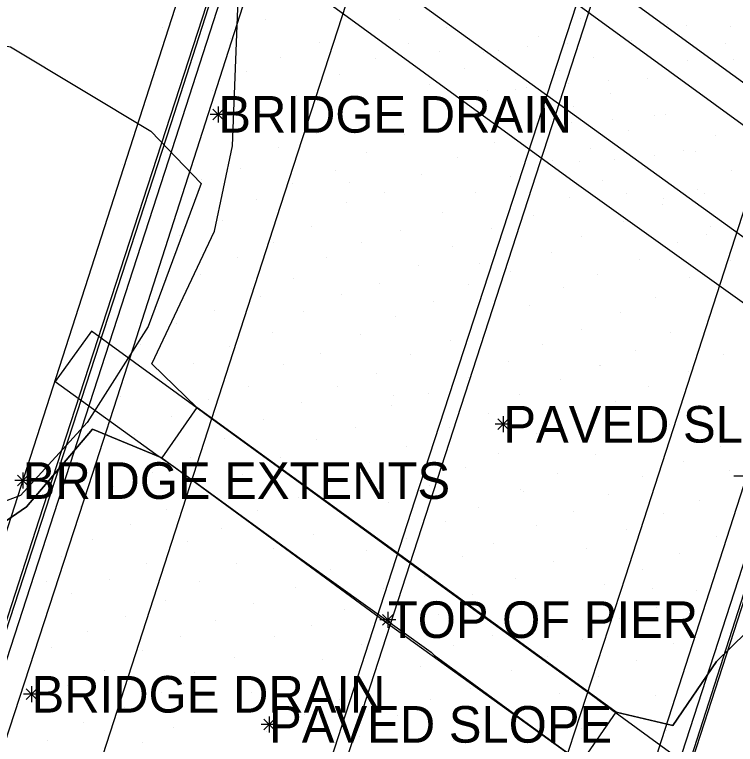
# Model space of a CAD drawing. Extents: x 0 to 1739264, y 0 to 465304.
# Drawn here: x 1738821.1 to 1738856.51, y 464637.2 to 464673.07 of the extents above; entities that cross this region are included whole.
import ezdxf

# ---------------------------------------------------------------- set-up
doc = ezdxf.new("R2010")
doc.units = 0
for name, color, linetype in [('Default', 7, 'Continuous'), ('S_Ground_SpotElevation', 7, 'Continuous'), ('S_Misc_MiscItems', 7, 'Continuous'), ('S_Terrain_Boundary', 7, 'Continuous'), ('S_Terrain_Flow_Arrows', 7, 'Continuous'), ('S_Terrain_Holes', 7, 'Continuous'), ('S_Terrain_Imported_Contours', 7, 'Continuous'), ('S_Terrain_Low_Points', 7, 'Continuous'), ('S_Terrain_Major_Contours_Label', 7, 'Continuous'), ('S_Terrain_Minor_Contours', 7, 'Continuous'), ('S_Terrain_Spots', 7, 'Continuous'), ('S_Terrain_Triangles', 7, 'Continuous'), ('S_Terrain_Voids', 7, 'Continuous'), ('S_Terrain_XSC', 7, 'Continuous'), ('S_Text', 7, 'Continuous')]:
    doc.layers.add(name, color=color, linetype=linetype)

# ---------------------------------------------------------------- blocks, each defined once
blk = doc.blocks.new('POINT_DISPLAY')
at = {"layer": 'Default'}
blk.add_line((0, 0), (0, 0), dxfattribs=at)

msp = doc.modelspace()

# ---------------------------------------------------------------- linework, layer by layer
at = {"layer": 'S_Misc_MiscItems'}
for p, q in [((1738831.105, 464668.563225), (1738831.105, 464667.777375)), ((1738831.497925, 464668.1703), (1738830.712075, 464668.1703)), ((1738831.367081, 464667.908219), (1738830.842919, 464668.432381)), ((1738831.367081, 464668.432381), (1738830.842919, 464667.908219)), ((1738845.371081, 464652.673819), (1738844.846919, 464653.197981)), ((1738845.371081, 464653.197981), (1738844.846919, 464652.673819)), ((1738845.109, 464653.328825), (1738845.109, 464652.542975)), ((1738845.501925, 464652.9359), (1738844.716075, 464652.9359)), ((1738821.499, 464650.559925), (1738821.499, 464649.774075)), ((1738821.891925, 464650.167), (1738821.106075, 464650.167)), ((1738821.761081, 464649.904919), (1738821.236919, 464650.429081)), ((1738821.761081, 464650.429081), (1738821.236919, 464649.904919)), ((1738857.224925, 464650.378), (1738856.439075, 464650.378)), ((1738839.435, 464643.723525), (1738839.435, 464642.937675)), ((1738839.697081, 464643.068519), (1738839.172919, 464643.592681)), ((1738839.697081, 464643.592681), (1738839.172919, 464643.068519)), ((1738839.827925, 464643.3306), (1738839.042075, 464643.3306)), ((1738822.191081, 464639.401119), (1738821.666919, 464639.925281)), ((1738822.191081, 464639.925281), (1738821.666919, 464639.401119)), ((1738821.929, 464640.056125), (1738821.929, 464639.270275)), ((1738822.321925, 464639.6632), (1738821.536075, 464639.6632)), ((1738833.865081, 464637.922419), (1738833.340919, 464638.446581)), ((1738833.865081, 464638.446581), (1738833.340919, 464637.922419)), ((1738833.603, 464638.577425), (1738833.603, 464637.791575)), ((1738833.995925, 464638.1845), (1738833.210075, 464638.1845))]:
    msp.add_line(p, q, dxfattribs=at)
at = {"layer": 'S_Terrain_Boundary'}
msp.add_lwpolyline([(1738472.502187, 464946.8812), (1738532.782491, 464903.138), (1738592.890188, 464859.1697), (1738654.956395, 464814.352699), (1738729.403905, 464760.335593), (1738775.1778, 464727.296302), (1738818.718499, 464695.4598), (1738870.5623, 464657.690711), (1738915.532399, 464624.999397), (1738974.4306, 464582.450111), (1739023.977193, 464546.580512), (1739063.9643, 464517.371711), (1739099.458196, 464491.667609), (1739137.386403, 464464.308906), (1739199.037587, 464419.570075), (1739224.736989, 464400.957526)], dxfattribs=at)
at = {"layer": 'S_Terrain_Flow_Arrows'}
msp.add_lwpolyline([(1739139.267385, 464454.910011), (1739130.590291, 464461.71009), (1739110.595495, 464477.929694), (1739082.297796, 464498.495307), (1739049.266698, 464522.52439), (1739001.084997, 464557.32859), (1738948.1471, 464595.782996), (1738903.076001, 464628.553901), (1738864.8372, 464656.393409), (1738827.215101, 464683.576698), (1738805.826267, 464699.079322)], dxfattribs=at)
at = {"layer": 'S_Terrain_Holes'}
msp.add_lwpolyline([(1739223.494985, 464399.203315), (1739206.639089, 464411.075385), (1739195.55071, 464418.42237), (1739183.070699, 464424.168708), (1739164.312002, 464433.463508), (1739147.939412, 464441.200599), (1739136.380086, 464447.050605), (1739129.442586, 464453.881599), (1739122.632696, 464461.219215), (1739111.531896, 464473.605506), (1739085.152105, 464493.350288), (1739018.993001, 464541.064887), (1738930.6419, 464605.24491), (1738870.0376, 464649.515296), (1738848.5874, 464664.834815), (1738811.620401, 464691.772605), (1738795.161496, 464705.215995), (1738777.6461, 464720.745506), (1738753.229703, 464739.785499), (1738719.607595, 464763.978797), (1738664.632497, 464803.914802), (1738578.72289, 464866.369498), (1738525.878194, 464904.395299), (1738470.625997, 464944.2677)], dxfattribs=at)
at = {"layer": 'S_Terrain_Imported_Contours'}
for points in [[(1738473.290487, 464948.323199), (1738505.971608, 464924.6372), (1738575.674489, 464873.970901), (1738632.579, 464832.433501), (1738679.622793, 464798.454398), (1738729.982305, 464762.007606), (1738794.297201, 464715.280997), (1738887.4227, 464647.539405), (1738945.963498, 464605.092414), (1739005.654607, 464561.761695), (1739053.679494, 464527.002113), (1739103.605703, 464490.864906), (1739143.362111, 464462.167487), (1739175.577993, 464438.694404), (1739209.519491, 464413.997199), (1739225.432607, 464402.38819)], [(1738861.917132, 464749.554455), (1738852.728099, 464720.865302), (1738834.137899, 464663.640296), (1738810.806299, 464591.494392), (1738798.57878, 464553.775144)], [(1738807.560265, 464547.101191), (1738818.883699, 464581.650611), (1738840.7733, 464649.227912), (1738859.7717, 464707.561698), (1738871.099421, 464743.042961)], [(1738871.2811, 464741.761298), (1738862.9528, 464715.336097), (1738835.861902, 464631.717414), (1738814.1443, 464564.731208), (1738808.177672, 464546.642409)], [(1738816.833754, 464540.526168), (1738828.844899, 464576.996803), (1738841.383399, 464615.664314), (1738851.1298, 464645.487891), (1738867.0642, 464694.79), (1738880.224773, 464736.284008)]]:
    msp.add_lwpolyline(points, dxfattribs=at)
at = {"layer": 'S_Terrain_Low_Points'}
for points in [[(1738792.605864, 464561.753915), (1738808.947702, 464611.187598), (1738829.7665, 464675.843208), (1738844.662601, 464721.815192), (1738854.169417, 464751.567291)], [(1738856.4555, 464747.969505), (1738838.244399, 464692.009101), (1738826.647699, 464655.847602), (1738824.734399, 464649.915199), (1738812.578801, 464612.657905), (1738795.808896, 464560.843085)], [(1738882.8352, 464729.589896), (1738865.96384, 464677.988066), (1738852.7233, 464636.911414), (1738851.7415, 464633.401588)], [(1738830.059193, 464653.760598), (1738827.847436, 464655.906259), (1738830.922601, 464662.43119), (1738831.796399, 464666.619514), (1738832.193102, 464676.781312)], [(1738855.273806, 464635.360066), (1738849.82601, 464639.341633), (1738849.6067, 464639.508537), (1738843.48614, 464643.947537), (1738842.990873, 464644.311317), (1738830.438266, 464653.454034), (1738830.074485, 464653.734539), (1738824.876175, 464657.51796), (1738823.095667, 464655.040075), (1738828.032899, 464651.473037)], [(1738807.696294, 464641.76682), (1738810.0528, 464643.531196), (1738813.668302, 464645.825294), (1738817.7753, 464646.198188), (1738821.681366, 464648.872297), (1738824.924348, 464652.689986), (1738828.329702, 464651.282111)], [(1738828.032899, 464651.473037), (1738828.923843, 464650.857843), (1738835.002801, 464646.444007), (1738835.226499, 464646.274299), (1738841.568099, 464641.72721), (1738841.7203, 464641.579993), (1738848.058099, 464636.947089), (1738848.372052, 464636.714783), (1738853.500766, 464632.982073), (1738855.273806, 464635.360066)], [(1738868.768823, 464650.421444), (1738864.5389, 464648.277198), (1738860.6901, 464646.271796), (1738855.580477, 464641.268905), (1738853.442893, 464638.131514), (1738850.651702, 464638.781989)]]:
    msp.add_lwpolyline(points, dxfattribs=at)
at = {"layer": 'S_Terrain_Major_Contours_Label'}
for points in [[(1738793.029831, 464557.898451), (1738803.9838, 464591.509406), (1738812.589898, 464618.183295), (1738822.305799, 464648.240607), (1738833.2133, 464681.803199), (1738842.84, 464711.786903), (1738850.196, 464734.470405), (1738856.340829, 464753.508813)], [(1738885.395159, 464732.452095), (1738884.2943, 464729.028999), (1738875.3401, 464701.327995), (1738857.6966, 464646.653999), (1738844.752799, 464606.659614), (1738829.9694, 464560.926002), (1738822.141572, 464536.77828)]]:
    msp.add_lwpolyline(points, dxfattribs=at)
at = {"layer": 'S_Terrain_Minor_Contours'}
for points in [[(1738812.939284, 464617.414493), (1738828.680813, 464665.938498), (1738835.762039, 464687.932576)], [(1738844.286302, 464607.201361), (1738848.147801, 464619.041197), (1738858.648407, 464651.422155), (1738867.135194, 464677.65191)]]:
    msp.add_lwpolyline(points, dxfattribs=at)
at = {"layer": 'S_Terrain_Spots'}
for points in [[(1738830.059193, 464653.760598), (1738827.847436, 464655.906259), (1738830.922601, 464662.43119), (1738831.796399, 464666.619514), (1738832.193102, 464676.781312)], [(1738828.329702, 464651.282111), (1738824.924348, 464652.689986), (1738821.681366, 464648.872297), (1738817.7753, 464646.198188), (1738813.668302, 464645.825294), (1738810.0528, 464643.531196), (1738807.696294, 464641.76682)], [(1738850.651702, 464638.781989), (1738853.442893, 464638.131514), (1738855.580477, 464641.268905), (1738860.6901, 464646.271796), (1738868.768823, 464650.421444)]]:
    msp.add_lwpolyline(points, dxfattribs=at)
at = {"layer": 'S_Terrain_Triangles'}
for points in [[(1738793.143077, 464557.8143), (1738794.925598, 464563.221652), (1738800.413936, 464580.303997), (1738804.057897, 464591.416999), (1738810.426301, 464610.960395), (1738818.2273, 464635.285011), (1738828.789701, 464667.726112), (1738838.3903, 464697.576408), (1738845.034101, 464718.107597), (1738853.3717, 464743.659003), (1738856.448989, 464753.432112)], [(1738885.339743, 464732.493165), (1738884.4636, 464729.823402), (1738878.6737, 464712.005698), (1738871.4064, 464689.647605), (1738862.8085, 464662.946113), (1738850.8758, 464625.801398), (1738841.409499, 464596.833595), (1738830.533101, 464562.882606), (1738822.877599, 464539.516792), (1738822.019587, 464536.864414)]]:
    msp.add_lwpolyline(points, dxfattribs=at)
at = {"layer": 'S_Terrain_Voids'}
msp.add_lwpolyline([(1738817.389901, 464647.94361), (1738813.363698, 464648.046302), (1738807.648099, 464650.569007), (1738803.023198, 464654.443092), (1738801.365201, 464659.29679), (1738803.535703, 464663.812293), (1738805.828698, 464666.531409), (1738807.832601, 464669.64289), (1738809.605501, 464673.041907), (1738814.253499, 464672.757392), (1738820.901601, 464671.487189), (1738827.797201, 464667.340095), (1738830.268499, 464664.764106), (1738827.659601, 464657.745795), (1738824.669401, 464653.024787), (1738821.380601, 464649.427711), (1738817.389901, 464647.94361)], dxfattribs=at)
at = {"layer": 'S_Terrain_XSC'}
msp.add_lwpolyline([(1738828.329702, 464651.282111), (1738839.572801, 464643.045295), (1738848.937102, 464636.293874), (1738850.651702, 464638.781989), (1738839.959664, 464646.566968), (1738830.059193, 464653.760598), (1738828.329702, 464651.282111)], dxfattribs=at)

# ---------------------------------------------------------------- block references
at = {"layer": 'S_Ground_SpotElevation'}
for p in [(1738833.405299, 464672.847526), (1738840.016491, 464672.838513), (1738848.904201, 464672.867424), (1738828.379395, 464672.41679), (1738838.086894, 464672.50341), (1738842.312907, 464672.424431), (1738853.171107, 464672.566399), (1738854.121685, 464672.562512), (1738856.248211, 464672.468914), (1738831.7205, 464671.881218), (1738836.059001, 464671.720817), (1738846.851298, 464671.995415), (1738851.389903, 464671.788689), (1738840.459102, 464671.677116), (1738846.276897, 464671.501415), (1738848.24879, 464671.644207), (1738856.025798, 464671.664726), (1738834.153606, 464670.984917), (1738841.970409, 464671.259411), (1738844.137707, 464671.230999), (1738844.894206, 464671.289299), (1738838.848598, 464670.939323), (1738849.523296, 464670.957024), (1738854.136394, 464670.796989), (1738856.421795, 464670.873211), (1738832.471202, 464670.282524), (1738843.206508, 464670.405083), (1738847.885203, 464670.321098), (1738837.055202, 464670.114799), (1738852.213802, 464669.955498), (1738831.911803, 464669.796396), (1738841.461803, 464669.624382), (1738848.295299, 464669.683392), (1738850.276012, 464669.839306), (1738830.827205, 464669.344475), (1738844.333507, 464669.35072), (1738845.715099, 464669.413994), (1738846.243694, 464669.479595), (1738850.392299, 464669.212089), (1738834.939204, 464669.092399), (1738839.417903, 464669.021904), (1738843.917201, 464668.835686), (1738854.982906, 464668.999321), (1738848.576594, 464668.549797), (1738833.172801, 464668.319816), (1738837.887004, 464668.123527), (1738853.086604, 464668.1502), (1738846.786708, 464667.778007), (1738848.47279, 464667.759716), (1738850.455913, 464667.936016), (1738852.547985, 464668.090191), (1738831.382106, 464667.699394), (1738842.267696, 464667.731621), (1738846.71751, 464667.704998), (1738851.239497, 464667.384025), (1738835.928905, 464667.242973), (1738840.237895, 464667.157524), (1738855.531398, 464667.152031), (1738844.6907, 464666.771599), (1738834.0451, 464666.552788), (1738849.378001, 464666.479301), (1738853.948207, 464666.413017), (1738854.556408, 464666.34251), (1738838.377101, 464666.278984), (1738842.837794, 464666.042778), (1738850.587993, 464665.95982), (1738852.552898, 464666.15559), (1738826.387605, 464665.720989), (1738847.537807, 464665.885429), (1738848.876812, 464665.861492), (1738832.182094, 464665.529411), (1738836.872798, 464665.398186), (1738852.108806, 464665.524895), (1738856.304805, 464665.411674), (1738830.283702, 464664.988396), (1738841.076305, 464665.198906), (1738845.482707, 464665.130485), (1738849.959407, 464664.912102), (1738834.758693, 464664.766289), (1738837.555899, 464664.809484), (1738839.285503, 464664.343315), (1738843.7243, 464664.353203), (1738851.146007, 464664.264691), (1738854.636897, 464664.469108), (1738855.004314, 464664.275006), (1738832.960796, 464664.007378), (1738837.412807, 464663.81591), (1738848.354701, 464664.069816), (1738852.980205, 464664.053997), (1738852.923701, 464663.740593), (1738842.128703, 464663.343071), (1738846.590297, 464663.221428), (1738831.309093, 464662.946831), (1738851.001094, 464662.897575), (1738835.682597, 464662.679985), (1738840.053004, 464662.484184), (1738844.512797, 464662.555717), (1738855.292003, 464662.662895), (1738829.220897, 464662.202324), (1738848.958507, 464662.18029), (1738855.095897, 464662.281719), (1738833.826701, 464661.856071), (1738838.160304, 464661.87719), (1738842.625499, 464661.696586), (1738853.6701, 464661.880302), (1738847.4593, 464661.397697), (1738832.0321, 464661.114799), (1738836.409999, 464661.11663), (1738851.793208, 464661.017082), (1738856.248195, 464660.989311), (1738840.943004, 464660.734917), (1738843.938399, 464660.821996), (1738830.216792, 464660.284172), (1738845.473399, 464660.423393), (1738849.752803, 464660.316704), (1738834.8063, 464660.100883), (1738839.026897, 464659.860405), (1738854.254298, 464660.134209), (1738832.761195, 464659.599419), (1738843.415904, 464659.825981), (1738848.065501, 464659.6632), (1738828.284801, 464659.481987), (1738833.190499, 464659.238409), (1738837.169597, 464659.338188), (1738852.575404, 464659.154472), (1738841.672908, 464658.974785), (1738830.908, 464658.550896), (1738835.307307, 464658.498405), (1738846.389598, 464658.755302), (1738850.845698, 464658.429985), (1738839.810298, 464658.217522), (1738855.188304, 464658.218803), (1738829.0507, 464657.886406), (1738844.332896, 464657.774895), (1738833.776698, 464657.466179), (1738848.930095, 464657.592399), (1738853.301906, 464657.450004), (1738838.097499, 464657.329216), (1738842.532298, 464657.058525), (1738827.303798, 464656.846489), (1738831.649501, 464656.761711), (1738847.021007, 464656.853813), (1738836.148097, 464656.412773), (1738840.561702, 464656.382622), (1738851.614604, 464656.564201), (1738855.952296, 464656.35302), (1738829.910503, 464655.939323), (1738845.385402, 464656.038383), (1738834.306697, 464655.862175), (1738849.8553, 464655.827184), (1738849.865001, 464655.822014), (1738854.193294, 464655.545891), (1738838.880305, 464655.41198), (1738843.381206, 464655.255424), (1738828.0731, 464655.146904), (1738847.899501, 464655.139824), (1738832.590404, 464654.774528), (1738836.961803, 464654.781486), (1738852.238399, 464654.793083), (1738826.282695, 464654.292595), (1738830.612102, 464654.155571), (1738839.703099, 464654.344091), (1738841.434901, 464654.428825), (1738845.894908, 464654.382805), (1738835.169505, 464653.994987), (1738839.616801, 464653.866997), (1738850.618297, 464654.064995), (1738844.373393, 464653.442192), (1738855.052501, 464653.7127), (1738828.7951, 464653.326774), (1738833.337703, 464653.155998), (1738848.732005, 464653.114921), (1738837.867107, 464652.787773), (1738842.450404, 464652.800712), (1738853.267406, 464652.929008), (1738827.003703, 464652.424309), (1738846.752605, 464652.49218), (1738831.415996, 464652.249687), (1738835.943599, 464652.174614), (1738851.262996, 464652.084526), (1738825.293605, 464651.610283), (1738840.330699, 464651.847221), (1738855.769801, 464651.860283), (1738829.745998, 464651.323723), (1738834.178401, 464651.296501), (1738844.891994, 464651.484917), (1738849.654399, 464651.446098), (1738838.534907, 464651.060722), (1738853.960796, 464651.110405), (1738827.858195, 464650.559624), (1738843.259608, 464650.802177), (1738847.751002, 464650.521477), (1738856.2445, 464650.639105), (1738832.291499, 464650.489494), (1738851.958003, 464650.384209), (1738825.933299, 464649.894524), (1738836.856303, 464650.154899), (1738841.4808, 464649.939079), (1738830.537593, 464649.645317), (1738845.960902, 464649.732109), (1738846.0904, 464649.623388), (1738850.279399, 464649.470878), (1738835.068202, 464649.345085), (1738839.4519, 464649.083305), (1738854.743999, 464649.194206), (1738824.3511, 464648.909477), (1738828.571895, 464648.76458), (1738843.915095, 464648.847587), (1738833.0368, 464648.692009), (1738837.483897, 464648.421623), (1738848.540706, 464648.6278), (1738852.990596, 464648.529411), (1738842.281306, 464648.165703), (1738826.776103, 464647.994377), (1738831.257198, 464647.797722), (1738846.732906, 464647.937919), (1738851.173, 464647.748711), (1738835.783, 464647.508903), (1738840.376598, 464647.304619), (1738855.570796, 464647.412102), (1738824.917094, 464647.280876), (1738829.581996, 464647.188774), (1738844.609904, 464647.092583), (1738833.819102, 464646.847893), (1738838.375896, 464646.740227), (1738849.197795, 464646.827385), (1738853.760997, 464646.597771), (1738823.417705, 464646.449028), (1738843.124293, 464646.425712), (1738827.599193, 464646.09539), (1738831.993404, 464646.085808), (1738847.561397, 464646.181999), (1738836.615794, 464645.816704), (1738851.943202, 464645.806877), (1738822.654401, 464645.212988), (1738825.779399, 464645.305717), (1738830.182597, 464645.212028), (1738841.220103, 464645.46392), (1738845.695399, 464645.371696), (1738834.908702, 464644.898674), (1738839.199504, 464644.84069), (1738850.090694, 464645.072624), (1738852.442899, 464644.846014), (1738854.581508, 464644.786003), (1738823.881206, 464644.635002), (1738843.571208, 464644.574211), (1738828.513698, 464644.27758), (1738832.849101, 464644.126701), (1738848.323299, 464644.272087), (1738837.325297, 464643.847893), (1738852.657207, 464643.944023), (1738826.532207, 464643.481499), (1738841.947597, 464643.591179), (1738846.578395, 464643.476311), (1738850.8399, 464643.401604), (1738830.990092, 464643.300529), (1738835.674297, 464643.023186), (1738840.127895, 464643.091728), (1738824.691493, 464642.731499), (1738829.243007, 464642.486992), (1738833.871303, 464642.527031), (1738844.554301, 464642.55767), (1738848.998302, 464642.34948), (1738822.887401, 464641.962089), (1738838.133495, 464642.131096), (1738842.6459, 464642.048515), (1738853.472697, 464642.140922), (1738827.358699, 464641.829582), (1738831.893794, 464641.469475), (1738836.247996, 464641.390617), (1738847.2653, 464641.543083), (1738851.642497, 464641.33538), (1738825.5144, 464640.834099), (1738841.047298, 464641.03698), (1738829.956599, 464640.727287), (1738845.531108, 464640.807793), (1738849.798305, 464640.517082), (1738829.4049, 464640.19071), (1738834.463893, 464640.403679), (1738839.104396, 464640.169121), (1738823.693095, 464640.105217), (1738828.315593, 464639.754631), (1738843.515407, 464639.933708), (1738832.746196, 464639.747795), (1738837.053798, 464639.414421), (1738847.860606, 464639.721184), (1738852.594096, 464639.60009), (1738841.535594, 464639.389274), (1738826.506999, 464639.004509), (1738830.743495, 464638.886284), (1738846.113795, 464638.866386), (1738850.633403, 464638.745109), (1738835.333705, 464638.656914), (1738839.886302, 464638.624016), (1738824.460399, 464638.25811), (1738828.913493, 464638.052788), (1738844.4062, 464638.067924), (1738848.952403, 464637.99572), (1738833.498195, 464637.852226), (1738853.126796, 464637.863396), (1738822.737498, 464637.373588), (1738827.391505, 464637.283317), (1738838.028102, 464637.586479), (1738842.670802, 464637.389824)]:
    msp.add_blockref('POINT_DISPLAY', p, dxfattribs=at)

# ---------------------------------------------------------------- texts
at = {"layer": 'S_Text'}
for s, p in [('BRIDGE DRAIN', (1738831.105, 464667.2703)), ('PAVED SLOPE', (1738845.109, 464652.0359)), ('BRIDGE EXTENTS', (1738821.499, 464649.267)), ('TOP OF PIER', (1738839.435, 464642.4306)), ('BRIDGE DRAIN', (1738821.929, 464638.7632)), ('PAVED SLOPE', (1738833.603, 464637.2845))]:
    msp.add_text(s, height=1.8, dxfattribs=at).set_placement(p)

doc.saveas('drawing.dxf')
